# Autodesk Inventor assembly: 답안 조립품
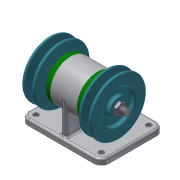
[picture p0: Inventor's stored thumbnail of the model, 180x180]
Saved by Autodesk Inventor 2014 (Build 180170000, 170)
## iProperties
Created: 2019-09
Part Number: 답안 조립품
Document SubType Name: Assembly
Designer: kh
Author: kh
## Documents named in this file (10)
- C:\Users\kh\Desktop\490904V1014\답안 조립품.iam
- C:\Users\kh\Desktop\490904V1014\본체.ipt
- C:\Users\kh\Desktop\490904V1014\V-벨트풀리.ipt
- C:\Users\kh\Desktop\490904V1014\너트 M10x1.ipt
- C:\Users\kh\Desktop\490904V1014\베어링 6004.ipt
- C:\Users\kh\Desktop\490904V1014\볼트 M4.ipt
- C:\Users\kh\Desktop\490904V1014\오일 실 17 30 5.ipt
- C:\Users\kh\Desktop\490904V1014\축.ipt
- C:\Users\kh\Desktop\490904V1014\커버.ipt
- C:\Users\kh\Desktop\490904V1014\키 5 x 5 x 12.ipt
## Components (2 placed, 1 different names)
1. V-벨트풀리:1 — Insert:11, Mate:2, Insert:17
2. V-벨트풀리:2 — Insert:16, Mate:3, Insert:18
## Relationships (6: Insert 4, Mate 2)
- Insert:11: V-벨트풀리:1
- Mate:2: V-벨트풀리:1
- Insert:16: V-벨트풀리:2
- Mate:3: V-벨트풀리:2
- Insert:17: V-벨트풀리:1
- Insert:18: V-벨트풀리:2
